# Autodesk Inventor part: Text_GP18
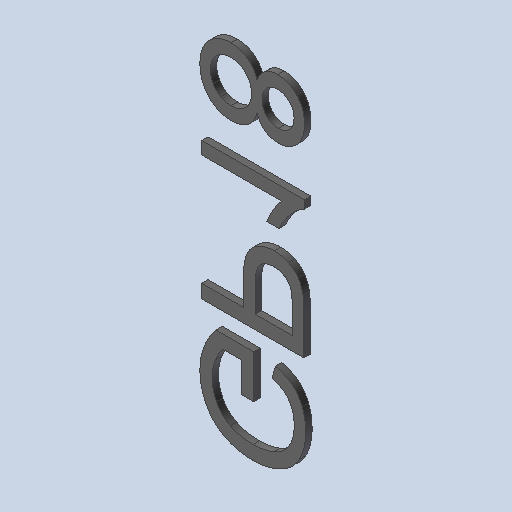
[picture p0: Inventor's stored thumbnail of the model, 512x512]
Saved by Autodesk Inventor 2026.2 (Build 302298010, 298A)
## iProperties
Created: 2026-10
Part Number: Text_GP18
Material: Générique
Document SubType Name: Modeling
Designer: mel
Density: 1 g/cm^3
Appearance: Par défaut
Author: mel
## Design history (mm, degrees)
feature "Base1"
feature "Base2"
feature "Base3"
feature "Base4"
node "Solide1"
node "Solide2"
node "Solide3"
node "Solide4"
